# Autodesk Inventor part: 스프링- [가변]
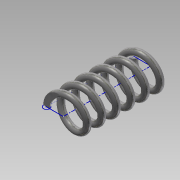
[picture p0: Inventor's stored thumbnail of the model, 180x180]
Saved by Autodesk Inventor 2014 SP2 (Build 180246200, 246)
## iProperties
Created: 2015-12
Part Number: 스프링- [가변]
Material: 강철, 탄소
Document SubType Name: Modeling
Designer: Administrator
Mass: 16.649 g
Surface Area: 28.5987 cm^2
Volume: 2.1155 cm^3
Density: 7.87 g/cm^3
Appearance: 반연마
Author: Administrator
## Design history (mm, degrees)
sketch "스케치1"
  geometry: L1 (0, 0)-(-8, 0); L2 (-8, 0)-(-8, 42); L3 (-8, 42)-(0, 42); L4 (0, 42)-(0, 0); C1 r 1.5 at (-8, 0)
  constraints: 8 end point, 2 parallel, 1 centre point, 1 coincident, 1 horizontal, 1 perpendicular
  dimensions: "d0" = 16 diameter of L2 L4; "d1" = 42 distance of L3.end L1.start (derived); "d2" = 3 diameter of C1
feature "코일1" sketch "스케치1" pitch "d3" = 10; turns "d5" = 6; dims "d4" = 42 (= d1), "d6" = 0, angle "d7" = 90 deg, angle "d8" = 90 deg, "d9" = 0, "d10" = 0
node "작업 평면1"
feature "분할1"
feature "분할2"
node "솔리드1"
other parameters: "d11" = 44
